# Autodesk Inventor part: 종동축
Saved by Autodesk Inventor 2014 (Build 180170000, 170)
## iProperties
Created: 2026-01
Part Number: 종동축
Material: 일반
Document SubType Name: Modeling
Designer: dg
Density: 1 g/cm^3
Appearance: 기본값
Author: dg
Author: jhkim
Creation Date: 2026-01-09
Sending System: Autodesk Inventor 2026
Preprocessor: ST-DEVELOPER v20.1
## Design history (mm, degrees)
node "종동축1"
node "솔리드1"
node "기준1"
